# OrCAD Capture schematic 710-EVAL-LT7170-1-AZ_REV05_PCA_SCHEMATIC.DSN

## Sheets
1 PAGE3
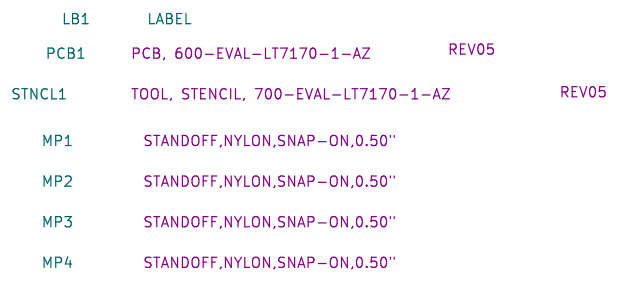
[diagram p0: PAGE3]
2 PAGE1: size Custom; title: WITH DIGITAL POWER SYSTEM MANAGEMENT; note: 20A 16V  DUAL PHASE STEP-DOWN SILENT SWITCHER
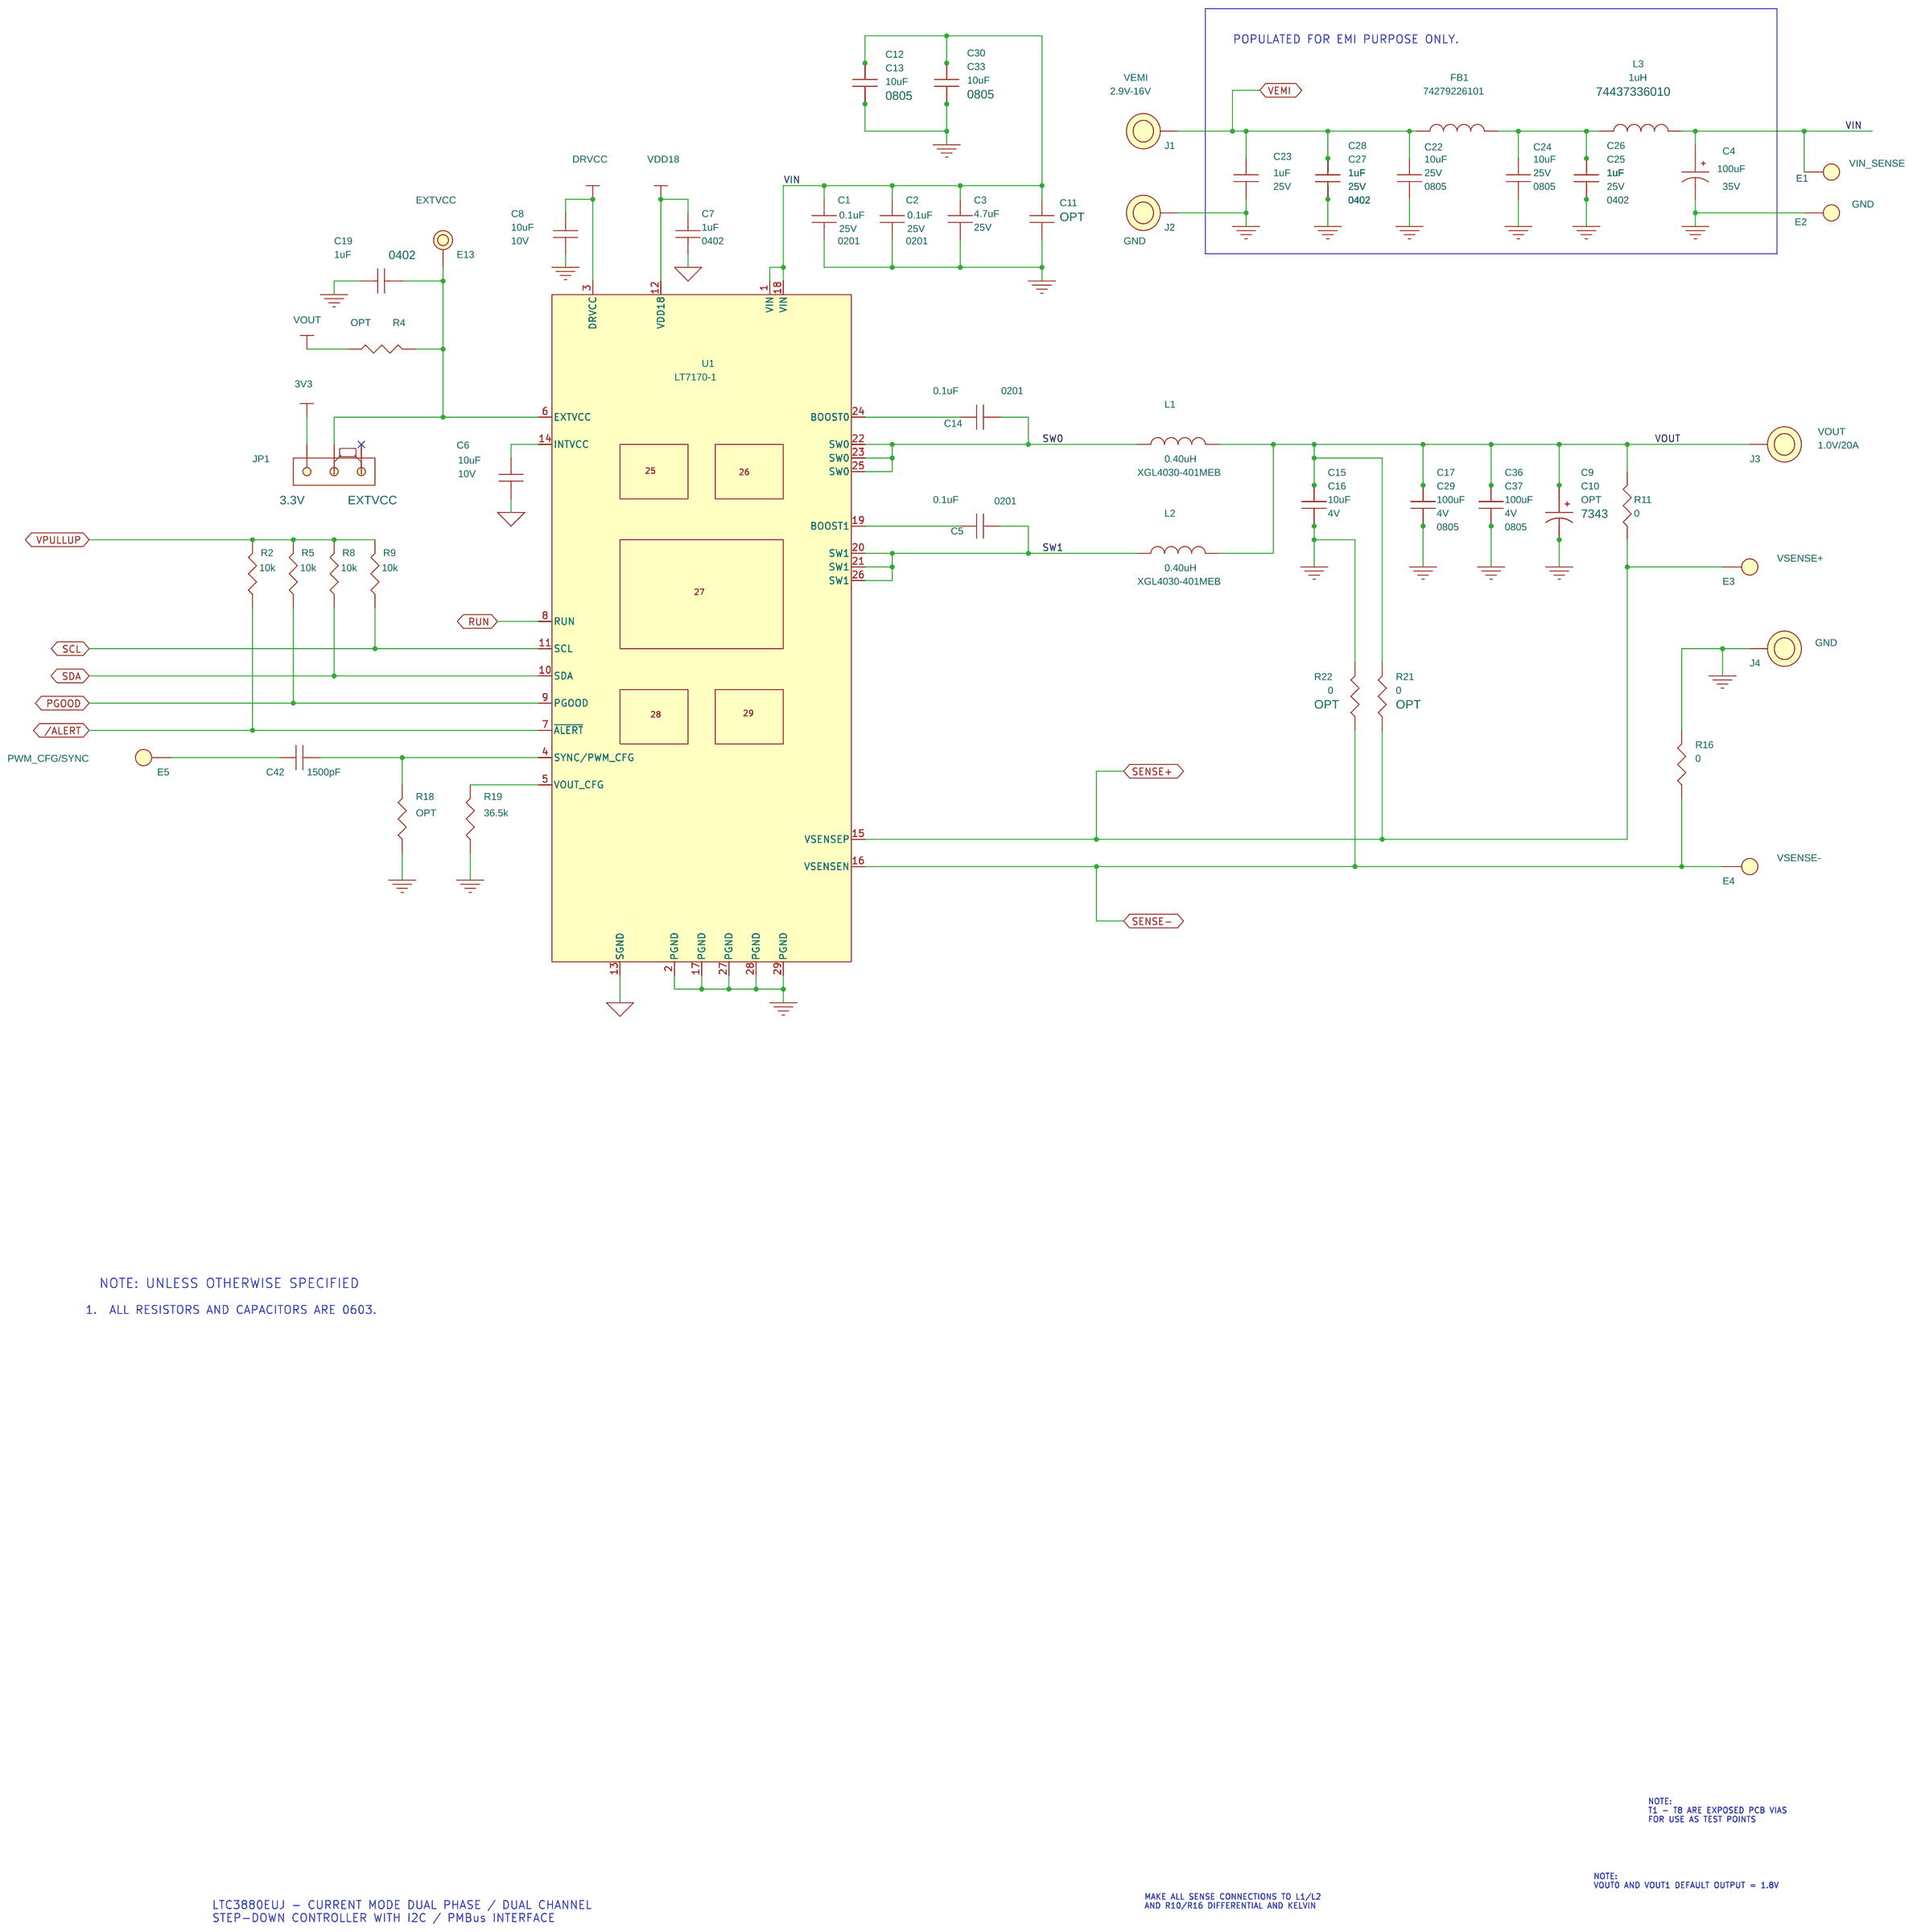
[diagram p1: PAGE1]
3 PAGE2: size Custom; title: WITH DIGITAL POWER SYSTEM MANAGEMENT; note: 20A 16V  DUAL PHASE STEP-DOWN SILENT SWITCHER
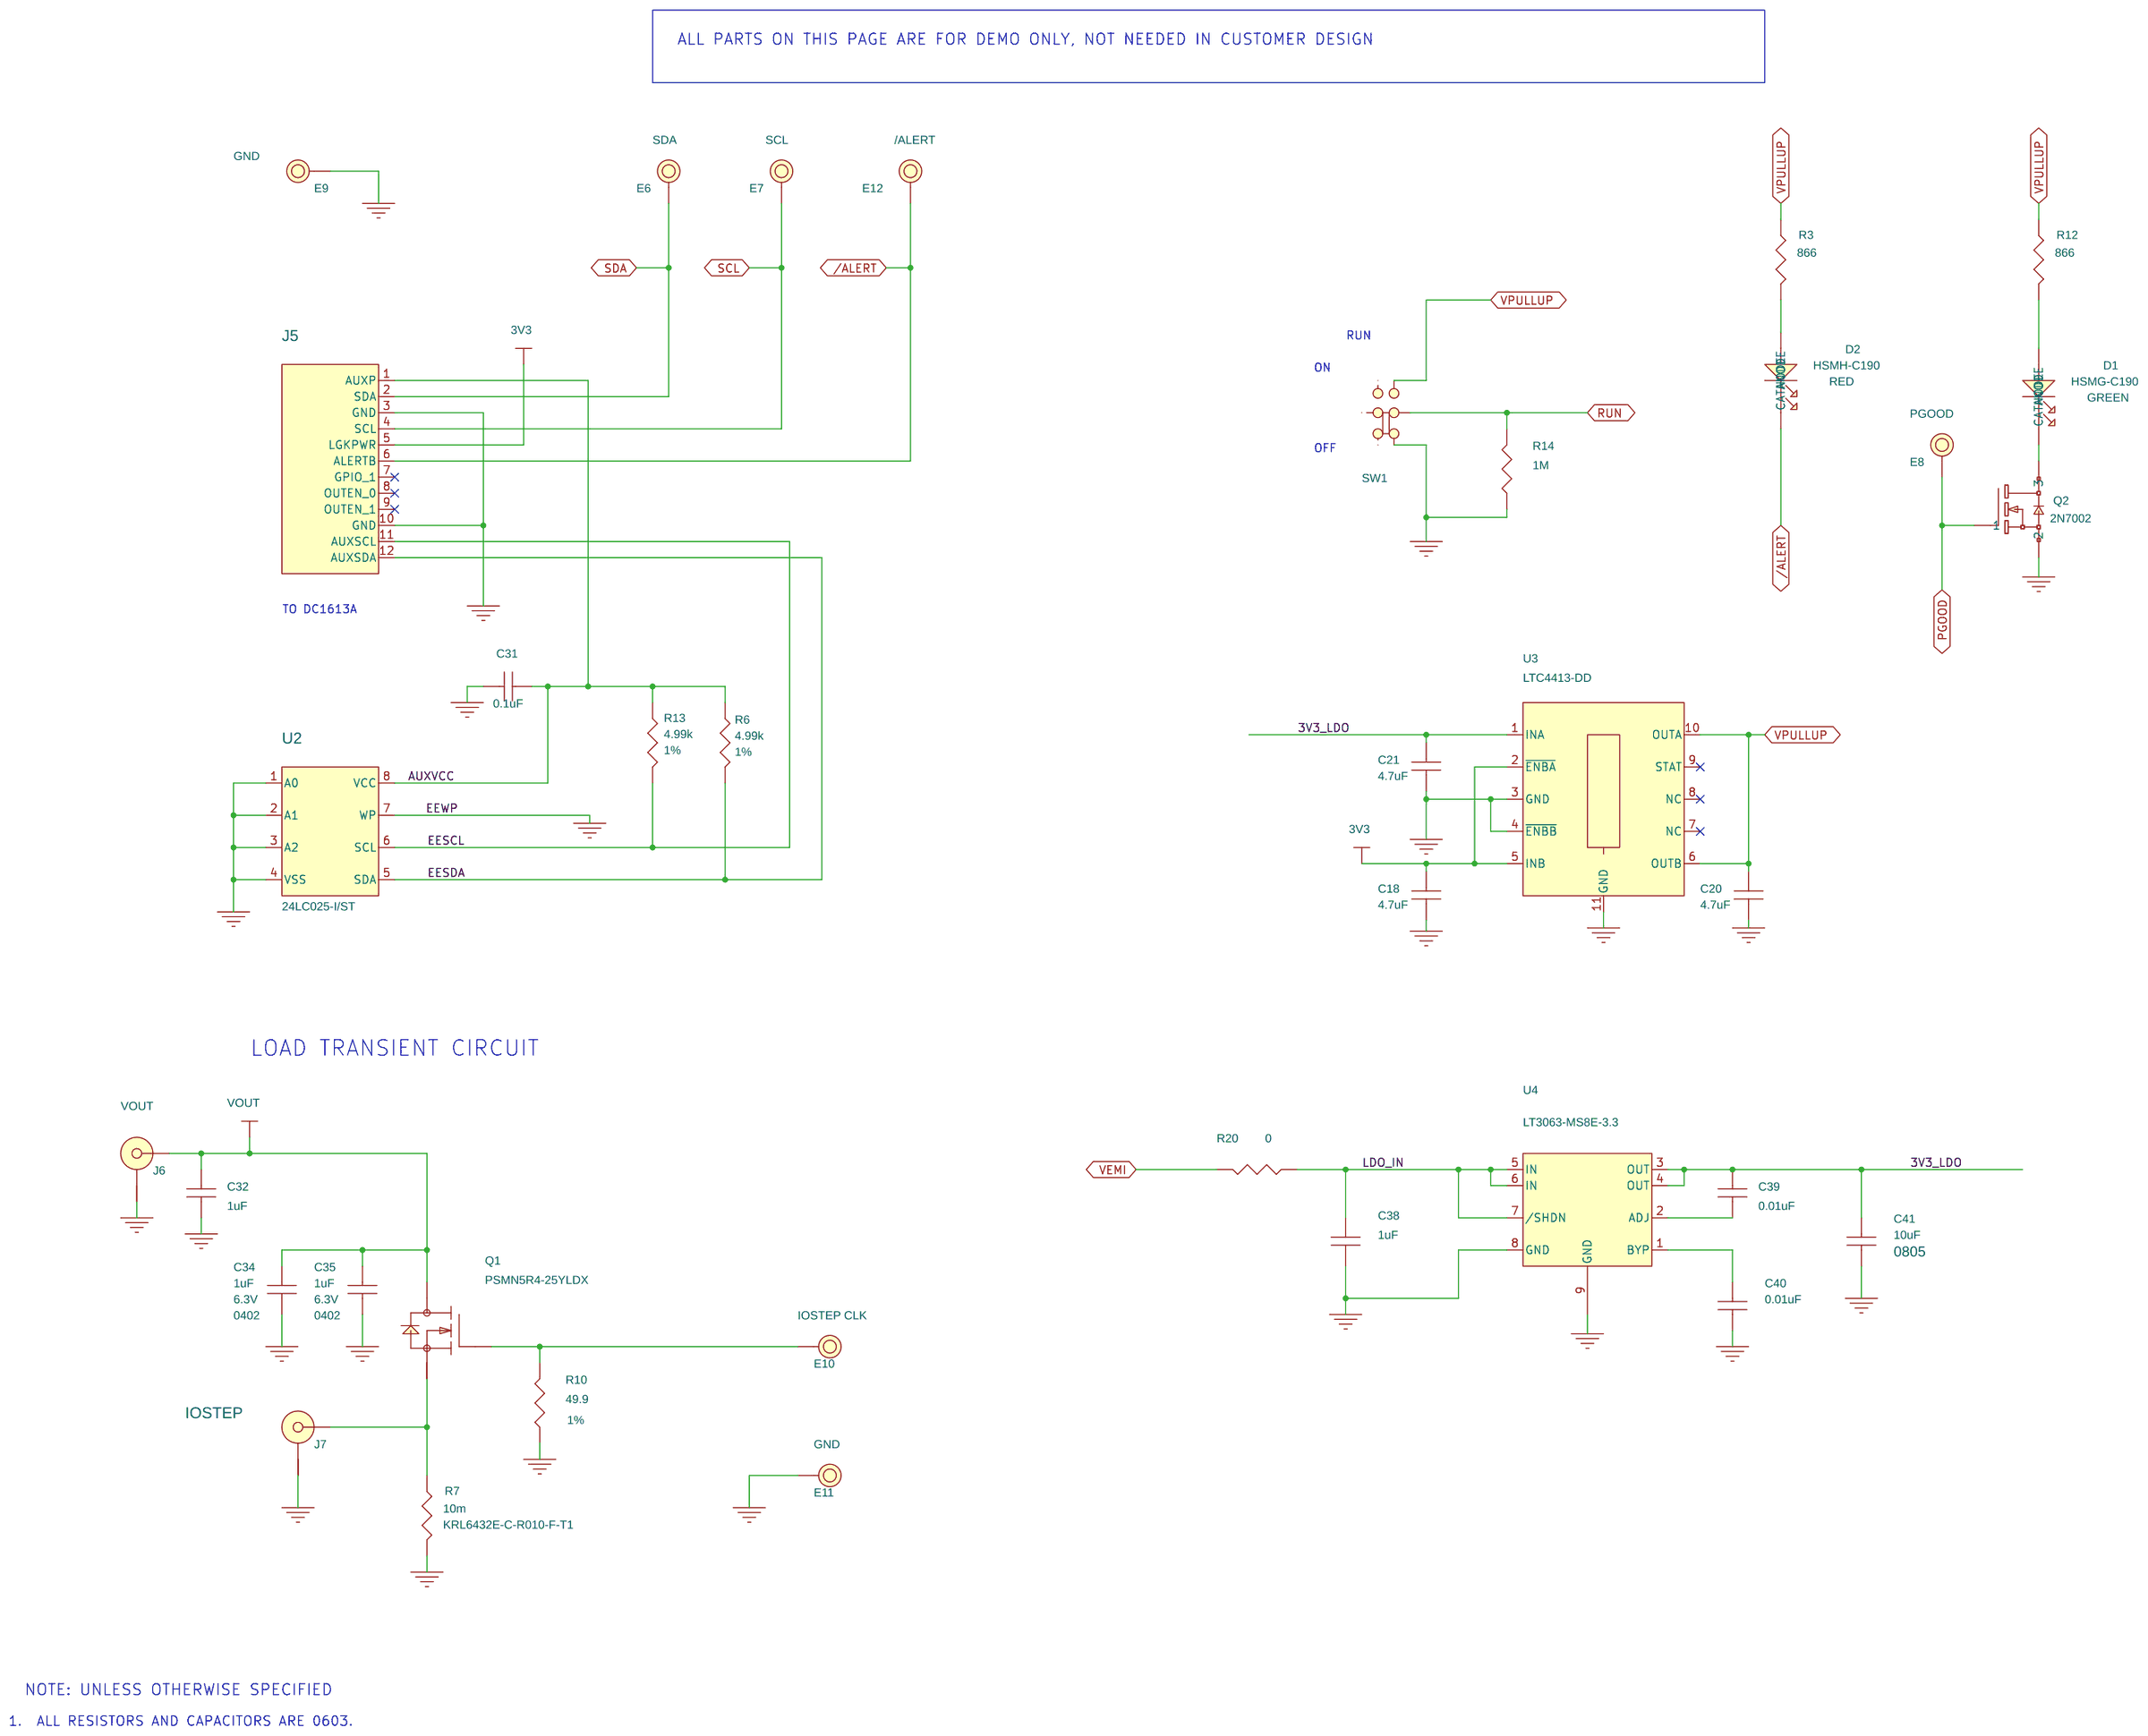
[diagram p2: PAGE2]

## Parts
sheet PAGE1
C1  0.1uF  [CC0201N]
C2  0.1uF  [CC0201N]
C3  4.7uF  [CC0603N]
C4  100uF  [PANASONIC_ZK_6.3X7.7]
C5  0.1uF  [CC0201N]
C6  10uF  [CC0603N]
C7  1uF  [CC0402N]
C8  10uF  [CC0603N]
C9  OPT  [CAPMP7343N]
C10  OPT  [CAPMP7343N]
C11  OPT  [CC0603N]
C12  10uF  [CC0805N]
C13  10uF  [CC0805N]
C14  0.1uF  [CC0201N]
C15  10uF  [CC0603N]
C16  10uF  [CC0603N]
C17  100uF  [CC0805N]
C19  1uF  [CC0402N]
C22  10uF  [CC0805N]
C23  1uF  [CC0603N]
C24  10uF  [CC0805N]
C25  1uF  [CC0402N]
C26  1uF  [CC0402N]
C27  1uF  [CC0402N]
C28  1uF  [CC0402N]
C29  100uF  [CC0805N]
C30  10uF  [CC0805N]
C33  10uF  [CC0805N]
C36  100uF  [CC0805N]
C37  100uF  [CC0805N]
C42  1500pF  [CC0603N]
E1  TEST POINT  [MILLMAX2308]
E2  TEST POINT  [MILLMAX2308]
E3  TEST POINT  [MILLMAX2308]
E4  TEST POINT  [MILLMAX2308]
E5  TEST POINT  [MILLMAX2308]
E13  TEST POINT  [MILLMAX2501]
FB1  100 OHMS@100MHz  [WURTH-74279226101]
J1  BANANA JACK  [KEY-575-4]
J2  BANANA JACK  [KEY-575-4]
J3  BANANA JACK  [KEY-575-4]
J4  BANANA JACK  [KEY-575-4]
JP1  HDR  [HD1X3-079]
L1  0.40uH  [COILCRAFT-XGL4030]
L2  0.40uH  [COILCRAFT-XGL4030]
L3  1uH  [WURTH-74437336010]
R2  10k  [CR0603N]
R4  OPT  [CR0603N]
R5  10k  [CR0603N]
R8  10k  [CR0603N]
R9  10k  [CR0603N]
R11  0  [CR0603N]
R16  0  [CR0603N]
R18  OPT  [CR0603N]
R19  36.5k  [CR0603N]
R21  0  [CR0603N]
R22  0  [CR0603N]
U1  LT7170-1  [LTC-LQFN-24-7065]
XJP1  SHUNT
sheet PAGE2
C18  4.7uF  [CC0603N]
C20  4.7uF  [CC0603N]
C21  4.7uF  [CC0603N]
C31  0.1uF  [CC0603N]
C32  1uF  [CC0402N]
C34  1uF  [CC0402N]
C35  1uF  [CC0402N]
C38  1uF  [CC0603N]
C39  0.01uF  [CC0603N]
C40  0.01uF  [CC0603N]
C41  10uF  [CC0805N]
D1  GREEN  [LED_0603]
D2  RED  [LED_0603]
E6  TEST POINT  [MILLMAX2501]
E7  TEST POINT  [MILLMAX2501]
E8  TEST POINT  [MILLMAX2501]
E9  TEST POINT  [MILLMAX2501]
E10  TEST POINT  [MILLMAX2501]
E11  TEST POINT  [MILLMAX2501]
E12  TEST POINT  [MILLMAX2501]
J5  HDR,SHROUDED  [HD2X6-079-MOLEX]
J6  RF,BNC  [CONNEX-112404]
J7  RF,BNC  [CONNEX-112404]
Q1  PSMN5R4-25YLDX  [NXP-LFPAK56]
Q2  2N7002  [SOT23-3N]
R3  866  [CR0603N]
R6  4.99k  [CR0603N]
R7  10m  [SUSUMU-KRL6432]
R10  49.9  [CR0603N]
R12  866  [CR0603N]
R13  4.99k  [CR0603N]
R14  1M  [CR0603N]
R20  0  [CR0603N]
SW1  DPDT  [CK-JS202011CQN]
U2  24LC025-I/ST  [MICROCHIP-TSSOP-8]
U3  LTC4413-DD  [LTC-DD-10-1699]
U4  LT3063-MS8E-3.3  [LTC-MS8E-8-1662]
sheet PAGE3
LB1  LABEL  [895-0154_REV01]
MP1  STANDOFF  [KEYSTONE_8829-8834]
MP2  STANDOFF  [KEYSTONE_8829-8834]
MP3  STANDOFF  [KEYSTONE_8829-8834]
MP4  STANDOFF  [KEYSTONE_8829-8834]
PCB1  PCB, 600-EVAL-LT7170-1-AZ
STNCL1  TOOL,STENCIL,700-EVAL-LT7170

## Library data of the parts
C1 C2 = CAP: CAP.,0.1uF,X6S,25V,10%,0201; CLASS: DISCRETE; Component: cap; Dielectric Type: X6S; FPLIST: CC0201N,CC0201L,CC0201M; Inventory Qty: 0; Manufacturer: Taiyo Yuden; Manufacturer PN: TMK063C6104KP-F; PART_NUMBER: 150-1861; Package Size: 0201; Part Number: TDK C3216X5R1E476M160AC; Part Type: CAP1206; Rated Voltage: 25V; Tolerance: 10%
C3 = CAP: CAP.,4.7uF,X6S,25V,10%,0603; CLASS: DISCRETE; Component: cap; Dielectric Type: X6S; FPLIST: CC0603N,CC0603L,CC0603M; Inventory Qty: 0; Manufacturer: MURATA; Manufacturer PN: GRM188C81E475KE11D; PART_NUMBER: 150-0798; Package Size: 0603; Part Number: TDK C3216X5R1E476M160AC; Part Type: CAP1206; Rated Voltage: 25V; Tolerance: 10%
C4 = CAP_P: CAP.,100uF,ALUM,35V,20%,SMD,AEC-Q200; CLASS: DISCRETE; Dielectric Type: ALUM; Inventory Qty: 0; Manufacturer: PANASONIC; Manufacturer PN: EEHZK1V101XP; PART_NUMBER: 150-1440; Package Size: SMD; Part Number: PANASONIC EEHZK1V101XP; Rated Voltage: 35V; Tolerance: 20%
C5 C14 = CAP: CAP.,0.1uF,X6S,25V,10%,0201; CLASS: DISCRETE; Component: cap; Dielectric Type: X6S; FPLIST: CC0201N,CC0201L,CC0201M; Inventory Qty: 0; Manufacturer: Taiyo Yuden; Manufacturer PN: TMK063C6104KP-F; PART_NUMBER: 150-1861; Package Size: 0201; Part Number: AVX 04023D104KAT2A; Rated Voltage: 25V; Tolerance: 10%
C6 = CAP: CAP.,10uF,X6S,10V,10%,0603,Interposer Termination,NO SUBS ALLOWED; CLASS: DISCRETE; Component: cap; Dielectric Type: X6S; FPLIST: CC0603N,CC0603L,CC0603M; Inventory Qty: 0; Manufacturer: MURATA; Manufacturer PN: ZRB18AC81A106KE01L; PART_NUMBER: 150-0797; Package Size: 0603; Part Number: TDK C3216X5R1E476M160AC; Part Type: CAP1206; Rated Voltage: 10V; Tolerance: 10%
C7 = CAP: CAP.,1uF,X7S,10V,10%,0402; CLASS: DISCRETE; Dielectric Type: X7S; FPLIST: CC0402N,CC0402L,CC0402M; Inventory Qty: 300; Manufacturer: MURATA; Manufacturer PN: GRM155C71A105KE11D; PART_NUMBER: 150-1445; Package Size: 0402; Part Number: MURATA ZRB18AC81A106KE01L; Rated Voltage: 10V; Tolerance: 10%
C8 = CAP: CAP.,10uF,X6S,10V,10%,0603,Interposer Termination,NO SUBS ALLOWED; CLASS: DISCRETE; Dielectric Type: X6S; FPLIST: CC0603N,CC0603L,CC0603M; Inventory Qty: 0; Manufacturer: MURATA; Manufacturer PN: ZRB18AC81A106KE01L; PART_NUMBER: 150-0797; Package Size: 0603; Part Number: MURATA ZRB18AC81A106KE01L; Rated Voltage: 10V; Tolerance: 10%
C9 C10 = CAP_P: CAP., OPTION, 7343; CLASS: DISCRETE; FPLIST: CAPMP7343N,CAPMP7343L,CAPMP7343M; PART_NUMBER: 150-0067; Package Size: 7343; Package Type: SMD; Part Number: OPTION
C11 = CAP: CAP., OPTION, 0603; CLASS: DISCRETE; Component: cap; FPLIST: CC0603N,CC0603L,CC0603M; PART_NUMBER: 150-3038; Package Size: 0603; Package Type: SMD; Part Number: TDK C3216X5R1E476M160AC; Part Type: CAP1206
C12 = CAP: CAP.,10uF,X7S,25V,10%,0805; CLASS: DISCRETE; Component: cap; Dielectric Type: X7S; FPLIST: CC0805N,CC0805L,CC0805M; Inventory Qty: 3000; Manufacturer: MURATA; Manufacturer PN: GRM21BC71E106KE11L; PART_NUMBER: 150-1813; Package Size: 0805; Package Type: SMD; Part Number: TDK C3216X5R1E476M160AC; Rated Voltage: 25V; Tolerance: 10%
C13 C30 C33 = CAP: CAP.,10uF,X7S,25V,10%,0805; CLASS: DISCRETE; Component: cap; Dielectric Type: X7S; FPLIST: CC0805N,CC0805L,CC0805M; Inventory Qty: 3000; Manufacturer: MURATA; Manufacturer PN: GRM21BC71E106KE11L; PART_NUMBER: 150-1813; Package Size: 0805; Package Type: SMD; Part Number: TDK C3216X5R1E476M160AC; Part Type: CAP1206; Rated Voltage: 25V; Tolerance: 10%
C15 C16 = CAP: CAP.,10uF,X7S,4V,20%,0603; CLASS: DISCRETE; Dielectric Type: X7S; FPLIST: CC0603N,CC0603L,CC0603M; Inventory Qty: 4000; Manufacturer: TDK; Manufacturer PN: C1608X7S0G106M080AB; PART_NUMBER: 150-1816; Package Size: 0603; Part Number: AVX 12106D107KAT2A; Rated Voltage: 4V; Temperature Coefficient: X7S; Tolerance: 20%
C17 C29 C36 C37 = CAP: CAP.,100uF,X6S,4V,20%,0805; CLASS: DISCRETE; Dielectric Type: X6S; FPLIST: CC0805N,CC0805L,CC0805M; Inventory Qty: 0; Manufacturer: MURATA; Manufacturer PN: GRM21BC80G107ME15L; PART_NUMBER: 150-0960; Package Size: 0805; Package Type: Surface Mount, MLCC; Part Number: AVX 12106D107KAT2A; Rated Voltage: 4V; Tolerance: 20%
C19 = CAP: CAP.,1uF,X7S,10V,10%,0402,AEC-Q200,NO SUBS. ALLOWED; CLASS: DISCRETE; Dielectric Type: X7S; FPLIST: CC0402N,CC0402L,CC0402M; Inventory Qty: 10000; Manufacturer: MURATA; Manufacturer PN: GCM155C71A105KE38D; PART_NUMBER: 150-0594; Package Size: 0402; Part Number: MURATA ZRB18AC81A106KE01L; Rated Voltage: 10V; Temperature Coefficient: X7S; Tolerance: 10%
C22 C24 = CAP: CAP.,10uF,X7S,25V,10%,0805; CLASS: DISCRETE; Dielectric Type: X7S; FPLIST: CC0805N,CC0805L,CC0805M; Inventory Qty: 3000; Manufacturer: MURATA; Manufacturer PN: GRM21BC71E106KE11L; PART_NUMBER: 150-1813; Package Size: 0805; Package Type: SMD; Part Number: TDK C3225X5R1H106K250AB; Rated Voltage: 25V; Tolerance: 10%
C23 = CAP: CAP.,1uF,X5R,25V,10%,0603; CLASS: DISCRETE; Dielectric Type: X5R; FPLIST: CC0603N,CC0603L,CC0603M; Inventory Qty: 24080; Manufacturer: AVX; Manufacturer PN: 06033D105KAT2A; PART_NUMBER: 150-0247; Package Size: 0603; Part Number: TDK CGA3E3X5R1H105K080AB; Rated Voltage: 25V; Tolerance: 10%
C25-C28 = CAP: CAP.,1uF,X5R,25V,10%,0402,NO SUBS ALLOWED; CLASS: DISCRETE; Dielectric Type: X5R; FPLIST: CC0402N,CC0402L,CC0402M; Inventory Qty: 10000; Manufacturer: MURATA; Manufacturer PN: GRM155R61E105KA12D; PART_NUMBER: 150-0822; Package Size: 0402; Part Number: MURATA GCM155R71H104KE02D; Rated Voltage: 25V; Tolerance: 10%
C42 = CAP: CAP.,1500pF,X7R,25V,10%,0603; CLASS: DISCRETE; Dielectric Type: X7R; FPLIST: CC0603N,CC0603L,CC0603M; Inventory Qty: 21092; Manufacturer: AVX; Manufacturer PN: 06033C152KAT2A; PART_NUMBER: 150-3370; Package Size: 0603; Rated Voltage: 25V; Tolerance: 10%
E1 = TEST_POINT_.156_MILL-MAX_2308: TEST POINT,TURRET,0.064" MTG. HOLE,PCB 0.062" THK; CLASS: IO; FPLIST: MILLMAX2308,MILLMAX2308-2; Inventory Qty: 1142083; Manufacturer: MILL-MAX; Manufacturer PN: 2308-2-00-80-00-00-07-0; PART_FIELD_1: VIN_SENSE; PART_NUMBER: 260-0004
E2 = TEST_POINT_.156_MILL-MAX_2308: TEST POINT,TURRET,0.064" MTG. HOLE,PCB 0.062" THK; CLASS: IO; FPLIST: MILLMAX2308,MILLMAX2308-2; Inventory Qty: 1142083; Manufacturer: MILL-MAX; Manufacturer PN: 2308-2-00-80-00-00-07-0; PART_FIELD_1: GND; PART_NUMBER: 260-0004
E3 = TEST_POINT_.156_MILL-MAX_2308: TEST POINT,TURRET,0.064" MTG. HOLE,PCB 0.062" THK; CLASS: IO; FPLIST: MILLMAX2308,MILLMAX2308-2; Inventory Qty: 1142083; Manufacturer: MILL-MAX; Manufacturer PN: 2308-2-00-80-00-00-07-0; PART_FIELD_1: VSENSE+; PART_NUMBER: 260-0004
E4 = TEST_POINT_.156_MILL-MAX_2308: TEST POINT,TURRET,0.064" MTG. HOLE,PCB 0.062" THK; CLASS: IO; FPLIST: MILLMAX2308,MILLMAX2308-2; Inventory Qty: 1142083; Manufacturer: MILL-MAX; Manufacturer PN: 2308-2-00-80-00-00-07-0; PART_FIELD_1: VSENSE-; PART_NUMBER: 260-0004
E5 = TEST_POINT_.156_MILL-MAX_2308: TEST POINT,TURRET,0.064" MTG. HOLE,PCB 0.062" THK; CLASS: IO; FPLIST: MILLMAX2308,MILLMAX2308-2; Inventory Qty: 1142083; Manufacturer: MILL-MAX; Manufacturer PN: 2308-2-00-80-00-00-07-0; PART_FIELD_1: PWM_CFG/SYNC; PART_NUMBER: 260-0004
E13 = TESTPOINT_.219_MILL-MAX_2501: TEST POINT,TURRET,0.094" MTG. HOLE,PCB 0.062" THK; CLASS: IO; Inventory Qty: 823526; Manufacturer: MILL-MAX; Manufacturer PN: 2501-2-00-80-00-00-07-0; PART_FIELD_01: EXTVCC; PART_NUMBER: 260-0003; Part Number: MILL-MAX 2501-2-00-80-00-00-07-0
FB1 = IND: IND.,100 OHMS@100MHz,FERRITE BEAD,25%,8A,6mOHMS,1812; CLASS: DISCRETE; Inventory Qty: 3043; Manufacturer: WURTH ELEKTRONIK; Manufacturer PN: 74279226101; PART_NUMBER: 200-0280; Package Size: 1812; Part Number: WURTH ELEKTRONIK 74279226101; Tolerance: 25%
J1 = BANANA_KEYSTONE-575-4: CONN.,BANANA JACK,FEMALE,THT,NON-INSULATED,SWAGE,0.218"; 1ST PART FIELD: 2.9V-16V; 2nd Part Field: VEMI; CLASS: IO; Inventory Qty: 203061; Manufacturer: KEYSTONE; Manufacturer PN: 575-4; PART_NUMBER: 250-0428
J2 = BANANA_KEYSTONE-575-4: CONN.,BANANA JACK,FEMALE,THT,NON-INSULATED,SWAGE,0.218"; 1ST PART FIELD: GND; CLASS: IO; Inventory Qty: 203061; Manufacturer: KEYSTONE; Manufacturer PN: 575-4; PART_NUMBER: 250-0428
J3 = BANANA_KEYSTONE-575-4: CONN.,BANANA JACK,FEMALE,THT,NON-INSULATED,SWAGE,0.218"; CLASS: IO; Inventory Qty: 203061; Manufacturer: KEYSTONE; Manufacturer PN: 575-4; PART_FIELD_01: VOUT; PART_NUMBER: 250-0428; Part_Field_02: 1.0V/20A
J4 = BANANA_KEYSTONE-575-4: CONN.,BANANA JACK,FEMALE,THT,NON-INSULATED,SWAGE,0.218"; CLASS: IO; Inventory Qty: 203061; Manufacturer: KEYSTONE; Manufacturer PN: 575-4; PART_FIELD_01: GND; PART_NUMBER: 250-0428; Part Number: MILL-MAX 2501-2-00-80-00-00-07-0
JP1 = 1X3: CONN.,HDR,MALE,1x3,2mm,VERT,ST,THT,NO SUBS. ALLOWED; 1st Part Field: 3.3V; 2nd Part Field: EXTVCC; CLASS: IO; Inventory Qty: 28997; Manufacturer: Wurth Elektronik; Manufacturer PN: 62000311121; PART_NUMBER: 250-0639
L1 L2 = IND: IND.,0.40uH,PWR,20%,22.5A,32.8mOHMS,SMD,AEC-Q200; CLASS: DISCRETE; Inventory Qty: 0; Manufacturer: COILCRAFT; Manufacturer PN: XGL4030-401MEB; PART_NUMBER: 200-0422; Package Size: SMD; Tolerance: 20%
L3 = IND: IND.,SHIELDED,1uH,20%,7.3A,14mOHMS,5030; CLASS: DISCRETE; Inventory Qty: 0; Manufacturer: WURTH ELEKTRONIK; Manufacturer PN: 74437336010; PART_NUMBER: TMP-8292; Package Size: 5030; Tolerance: 20%
R2 R5 R8 R9 = RES: RES.,10k OHMS,1%,1/10W,0603,AEC-Q200; CLASS: DISCRETE; FPLIST: CR0603N,CR0603L,CR0603M; Inventory Qty: 194448; Manufacturer: VISHAY; Manufacturer PN: CRCW060310K0FKEA; PART_NUMBER: 100-2012; Package Size: 0603; Part Number: VISHAY CRCW060310K0FKEA; Part Type: CR0402; Rated Power: 1/10W; Temperature Coefficient: +/-100ppm/C; Tolerance: 1%
R4 = RES: RES., OPTION, 0603; CLASS: DISCRETE; FPLIST: CR0603N,CR0603L,CR0603M; PART_NUMBER: 100-2374; Package Size: 0603; Part Number: OPTION
R11 R16 = RES: RES.,0 OHM,1/10W,0603,AEC-Q200; CLASS: DISCRETE; FPLIST: CR0603N,CR0603L,CR0603M; Inventory Qty: 676258; Manufacturer: VISHAY; Manufacturer PN: CRCW06030000Z0EA; PART_NUMBER: 100-0009; Package Size: 0603; Part Number: VISHAY CRCW06030000Z0EA; Rated Power: 1/10W
R18 = RES: RES., OPTION, 0603; CLASS: DISCRETE; FPLIST: CR0603N,CR0603L,CR0603M; PART_NUMBER: 100-2374; Package Size: 0603; Part Type: CR0402
R19 = RES: RES.,36.5k OHMS,1%,1/10W,0603; CLASS: DISCRETE; FPLIST: CR0603N,CR0603L,CR0603M; Inventory Qty: 32942; Manufacturer: VISHAY; Manufacturer PN: CRCW060336K5FKEA; PART_NUMBER: 100-0337; Package Size: 0603; Part Number: TBD; Part Type: CR0402; Rated Power: 1/10W; Temperature Coefficient: 100ppm; Tolerance: 1%
R21 R22 = RES: RES.,0 OHM,1/10W,0603,AEC-Q200; BOM Notes: OPT; CLASS: DISCRETE; FPLIST: CR0603N,CR0603L,CR0603M; Inventory Qty: 700742; Manufacturer: VISHAY; Manufacturer PN: CRCW06030000Z0EA; PART_NUMBER: 100-0009; Package Size: 0603; Part Number: VISHAY CRCW06030000Z0EA; Rated Power: 1/10W
U1 = LT7170-1-LQFN_1: IC,REGULATOR,LQFN-24, 12A,16V  DUAL PHASE STEP-DOWN SILENT SWITCHER; CLASS: IC; Inventory Qty: 0; Manufacturer: ANALOG DEVICES; Manufacturer PN: LT7170RV-1#TRPBF; PART_NUMBER: LOCAL-LT7170-1-LQFN; Package Type: LQFN
XJP1 = SHUNT_2MM: CONN.,SHUNT,FEMALE,2-POS,2mm; CLASS: IO; Inventory Qty: 64675; Manufacturer: Wurth Elektronik; Manufacturer PN: 60800213421; PART_NUMBER: 250-0485; Part Number: Wurth Elektronik 60800213421
C18 C20 C21 = CAP: CAP.,4.7uF,X5R,25V,10%,0603; CLASS: DISCRETE; Dielectric Type: X5R; FPLIST: CC0603N,CC0603L,CC0603M; Inventory Qty: 10846; Manufacturer: MURATA; Manufacturer PN: GRM188R61E475KE15D; PART_NUMBER: 150-0445; Package Size: 0603; Part Number: TDK C1608X7S0J475K080AC; Rated Voltage: 25V; Tolerance: 10%
C31 = CAP: CAP.,0.1uF,X7R,10V,20%,0603; CLASS: DISCRETE; Dielectric Type: X7R; FPLIST: CC0603N,CC0603L,CC0603M; Inventory Qty: 17762; Manufacturer: AVX; Manufacturer PN: 0603ZC104MAT2A; PART_NUMBER: 150-3258; Package Size: 0603; Part Number: AVX 0603ZC104MAT2A; Rated Voltage: 10V; Tolerance: 20%
C32 C34 C35 = CAP: CAP.,1uF,X7R,6.3V,10%,0402; CLASS: DISCRETE; Dielectric Type: X7R; FPLIST: CC0402N,CC0402L,CC0402M; Inventory Qty: 20000; Manufacturer: MURATA; Manufacturer PN: GRM155R70J105KA12D; PART_NUMBER: 150-2328; Package Size: 0402; Part Number: MURATA GCM188R71H103KA37D; Rated Voltage: 6.3V; Tolerance: 10%
C38 = CAP: CAP.,1uF,X7R,50V,10%,0603; CLASS: DISCRETE; Dielectric Type: X7R; FPLIST: CC0603N,CC0603L,CC0603M; Inventory Qty: 15823; Manufacturer: AVX; Manufacturer PN: 06035C105KAT2A; PART_NUMBER: 150-2333; Package Size: 0603; Part Number: MURATA GCM188R71H103KA37D; Rated Voltage: 50V; Tolerance: 10%
C39 C40 = CAP: CAP.,0.01uF,X7R,25V,10%,0603,AEC-Q200; CLASS: DISCRETE; Dielectric Type: X7R; FPLIST: CC0603N,CC0603L,CC0603M; Inventory Qty: 54846; Manufacturer: AVX; Manufacturer PN: 06033C103K4Z2A; PART_NUMBER: 150-0440; Package Size: 0603; Part Number: MURATA GCM188R71H103KA37D; Rated Voltage: 25V; Tolerance: 10%
C41 = CAP: CAP.,10uF,X7R,10V,10%,0805; CLASS: DISCRETE; Dielectric Type: X7R; FPLIST: CC0805N,CC0805L,CC0805M; Inventory Qty: 25564; Manufacturer: AVX; Manufacturer PN: 0805ZC106KAT2A; PART_NUMBER: 150-3001; Package Size: 0805; Part Number: MURATA GCM188R71H103KA37D; Rated Voltage: 10V; Tolerance: 10%
D1 = LED: LED,GREEN,DIFFUSED,0603; CLASS: DISCRETE; Inventory Qty: 5000; Manufacturer: BROADCOM INC.; Manufacturer PN: HSMG-C190; PART_NUMBER: 270-0131; Package Type: 0603; Part Number: WURTH ELEK. 150060GS75000
D2 = LED: LED,RED,DIFFUSED,0603; CLASS: DISCRETE; Inventory Qty: 4000; Manufacturer: BROADCOM INC.; Manufacturer PN: HSMH-C190; PART_NUMBER: 270-0156; Package Type: 0603; Part Number: WURTH ELEK. 150060GS75000
E6 = TESTPOINT_.219_MILL-MAX_2501: TEST POINT,TURRET,0.094" MTG. HOLE,PCB 0.062" THK; CLASS: IO; Inventory Qty: 823526; Manufacturer: MILL-MAX; Manufacturer PN: 2501-2-00-80-00-00-07-0; PART_FIELD_01: SDA; PART_NUMBER: 260-0003; Part Number: MILL-MAX 2501-2-00-80-00-00-07-0
E7 = TESTPOINT_.219_MILL-MAX_2501: TEST POINT,TURRET,0.094" MTG. HOLE,PCB 0.062" THK; CLASS: IO; Inventory Qty: 823526; Manufacturer: MILL-MAX; Manufacturer PN: 2501-2-00-80-00-00-07-0; PART_FIELD_01: SCL; PART_NUMBER: 260-0003; Part Number: MILL-MAX 2501-2-00-80-00-00-07-0
E8 = TESTPOINT_.219_MILL-MAX_2501: TEST POINT,TURRET,0.094" MTG. HOLE,PCB 0.062" THK; CLASS: IO; Inventory Qty: 823526; Manufacturer: MILL-MAX; Manufacturer PN: 2501-2-00-80-00-00-07-0; PART_FIELD_01: PGOOD; PART_NUMBER: 260-0003; Part Number: MILL-MAX 2501-2-00-80-00-00-07-0
E9 E11 = TESTPOINT_.219_MILL-MAX_2501: TEST POINT,TURRET,0.094" MTG. HOLE,PCB 0.062" THK; CLASS: IO; Inventory Qty: 823526; Manufacturer: MILL-MAX; Manufacturer PN: 2501-2-00-80-00-00-07-0; PART_FIELD_01: GND; PART_NUMBER: 260-0003; Part Number: MILL-MAX 2501-2-00-80-00-00-07-0
E10 = TESTPOINT_.219_MILL-MAX_2501: TEST POINT,TURRET,0.094" MTG. HOLE,PCB 0.062" THK; CLASS: IO; Inventory Qty: 823526; Manufacturer: MILL-MAX; Manufacturer PN: 2501-2-00-80-00-00-07-0; PART_FIELD_01: IOSTEP CLK; PART_NUMBER: 260-0003; Part Number: MILL-MAX 2501-2-00-80-00-00-07-0
E12 = TESTPOINT_.219_MILL-MAX_2501: TEST POINT,TURRET,0.094" MTG. HOLE,PCB 0.062" THK; CLASS: IO; Inventory Qty: 823526; Manufacturer: MILL-MAX; Manufacturer PN: 2501-2-00-80-00-00-07-0; PART_FIELD_01: /ALERT; PART_NUMBER: 260-0003; Part Number: MILL-MAX 2501-2-00-80-00-00-07-0
J5 = CONN._FCI_12_POS_2MM: CONN.,HDR,SHROUDED,MALE,2x6,2mm,VERT,ST,THT; CLASS: IO; FPLIST: HD2X6-079-MOLEX,AMPHENOL-FCI-9814-X06-12; Inventory Qty: 12768; Manufacturer: AMPHENOL; Manufacturer PN: 98414-G06-12ULF; PART_NUMBER: 250-0433; Part Number: FCI 98414-G06-12ULF
J6 = BNC_50_OHM_112404_B: CONN.,RF,BNC,RCPT,JACK,5-PIN,ST,THT,50 OHMS; 1ST PART FIELD: VOUT; CLASS: IO; Inventory Qty: 80023; Manufacturer: AMPHENOL RF; Manufacturer PN: 112404; PART_NUMBER: 250-0427; Part Number: AMPHENOL RF 112404
J7 = BNC_50_OHM_112404_B: CONN.,RF,BNC,RCPT,JACK,5-PIN,ST,THT,50 OHMS; 1ST PART FIELD: IOSTEP; CLASS: IO; Inventory Qty: 80023; Manufacturer: AMPHENOL RF; Manufacturer PN: 112404; PART_NUMBER: 250-0427; Part Number: AMPHENOL RF 112404
Q1 = 5P_N-CH_TYPE1D_0: XSTR.,MOSFET,N-CH,25V,70A,LFPAK55,Power-SO8; CLASS: DISCRETE; Inventory Qty: 1456; Manufacturer: NEXPERIA; PART_NUMBER: 240-0436; Package Size: SC-100, SOT-669; Package Type: LFPAK55,Power-SO8; Rated Power: 47W (Tc); Rated Voltage: 25V
Q2 = 2N7002_SOT-23: XSTR.,MOSFET,N-CH,60V,300mA,SOT-23-3 (TO-236); CLASS: DISCRETE; Inventory Qty: 6460; Manufacturer: VISHAY; Manufacturer PN: 2N7002K-T1-GE3; PART_NUMBER: 240-0125; Package Size: SOT-23; Package Type: SOT-23-3 (TO-236); Part Number: VISHAY 2N7002K-T1-GE3; Rated Voltage: 60V
R3 R12 = RES: RES.,866 OHMS,1%,1/10W,0603,AEC-Q200; CLASS: DISCRETE; FPLIST: CR0603N,CR0603L,CR0603M; Inventory Qty: 30000; Manufacturer: VISHAY; Manufacturer PN: CRCW0603866RFKEA; PART_NUMBER: 100-0436; Package Size: 0603; Part Number: VISHAY CRCW0603200RFKEA; Rated Power: 1/10W; Temperature Coefficient: 100ppm; Tolerance: 1%
R6 R13 = RES: RES.,4.99k OHMS,1%,1/10W,0603,AEC-Q200; CLASS: DISCRETE; FPLIST: CR0603N,CR0603L,CR0603M; Inventory Qty: 89391; Manufacturer: PANASONIC; Manufacturer PN: ERJ3EKF4991V; PART_NUMBER: 100-2510; Package Size: 0603; Part Number: VISHAY CRCW06034K99FKEA; Rated Power: 1/10W; Temperature Coefficient: 100ppm; Tolerance: 1%
R7 = RES: RES.,10m OHMS,1%,3W,6.3 X3.1mm,AEC-Q200 LONG-SIDE TERM; CLASS: DISCRETE; Inventory Qty: 0; Manufacturer: SUSUMU; Manufacturer PN: KRL6432E-C-R010-F-T1; PART_NUMBER: 100-1792; Package Size: 6.3 X3.1mm; Rated Power: 3W; Temperature Coefficient: 50PPM; Tolerance: 1%
R10 = RES: RES.,49.9 OHMS,1%,1/10W,0603; CLASS: DISCRETE; FPLIST: CR0603N,CR0603L,CR0603M; Inventory Qty: 58078; Manufacturer: PANASONIC; Manufacturer PN: ERJ3EKF49R9V; PART_NUMBER: 100-0115; Package Size: 0603; Part Number: VISHAY CRCW060310K0FKEA; Rated Power: 1/10W; Temperature Coefficient: +/-100ppm; Tolerance: 1%
R14 = RES: RES.,1M OHM,1%,1/10W,0603,AEC-Q200; CLASS: DISCRETE; FPLIST: CR0603N,CR0603L,CR0603M; Inventory Qty: 31399; Manufacturer: NIC; Manufacturer PN: NRC06F1004TRF; PART_NUMBER: 100-0119; Package Size: 0603; Part Number: VISHAY CRCW060310R0JNEA; Rated Power: 1/10W; Temperature Coefficient: 100ppm/C; Tolerance: 1%
R20 = RES: RES.,0 OHM,1/10W,0603,AEC-Q200; CLASS: DISCRETE; FPLIST: CR0603N,CR0603L,CR0603M; Inventory Qty: 676258; Manufacturer: VISHAY; Manufacturer PN: CRCW06030000Z0EA; PART_NUMBER: 100-0009; Package Size: 0603; Part Number: VISHAY CRCW060310R0JNEA; Rated Power: 1/10W
SW1 = SW-DPDT-JS202011CQN_ALT4: SWITCH,SLIDE,DPDT,0.3A,6VDC,PTH; CLASS: DISCRETE; Inventory Qty: 32171; Manufacturer: C&K; Manufacturer PN: JS202011CQN; PART_NUMBER: 430-0039
U2 = 24LC025-I_ST_TSSOP-8: IC, MEMORY,EEPROM,2Kb (256x8),TSSOP-8,400kHz; CLASS: IC; Inventory Qty: 19510; Manufacturer: Microchip; PART_NUMBER: 380-0087; Package Size: TSSOP-8; Package Type: TSSOP-8; Part Number: MICROCHIP 24LC025-I/ST
U3 = LTC4413-DD: IC,DUAL 2.6A, 2.5V-5.5V IDEAL DIO,10DFN; CLASS: IC; Inventory Qty: 0; Manufacturer: ANALOG DEVICES; Manufacturer PN: LTC4413EDD#PBF; PART_NUMBER: LTC4413EDD#PBF; Package Size: 3mmX3mm; Package Type: 10DFN
U4 = LT3063-MS8E-X: IC,200mA LDO LINEAR REGULATOR,MSOP-8 (MS8E); CLASS: IC; Inventory Qty: 0; Manufacturer: LINEAR TECH.; Manufacturer PN: LT3063EMS8E-3.3#PBF; PART_NUMBER: LT3063EMS8E-3.3#PBF; Package Type: MSOP-8 (MS8E)
LB1 = BLANK_LABEL: LABEL SPEC, DEMO BOARD SERIAL NUMBER; Inventory Qty: 0; Manufacturer: BRADY; Manufacturer PN: THT-96-717-10; PART_NUMBER: 895-0154
MP1-MP4 = BLANK_MECHANICAL_PART: STANDOFF,NYLON,SNAP-ON,0.50"; CLASS: DISCRETE; Inventory Qty: 214842; Manufacturer: KEYSTONE; Manufacturer PN: 8833; PART_NUMBER: 763-0007
PCB1 = BLANK_PCB_PART: BOM Notes: REV05; CLASS: DISCRETE; Inventory Qty: 0; Manufacturer: ADI APPROVED SUPPLIER; Manufacturer PN: 600-EVAL-LT7170-1-AZ; PART_NUMBER: 600-EVAL-LT7170-1-AZ
STNCL1 = BLANK_STENCIL_PART: TOOL, STENCIL, 700-EVAL-LT7170-1-AZ; BOM Notes: REV05; CLASS: DISCRETE; Inventory Qty: 0; Manufacturer: ADI APPROVED SUPPLIER; Manufacturer PN: 830-EVAL-LT7170-1-AZ; PART_NUMBER: 830-EVAL-LT7170-1-AZ

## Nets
3V3: C18.1 J5.5(LGKPWR) JP1.1 U3.2(~{ENBA}) U3.5(INB)
3V3_LDO: C21.1 C39.1 C41.1 U3.1(INA) U4.3(OUT) U4.4(OUT)
GND: C1.2 C2.2 C3.2 C4.2 C8.1 C9.2 C10.2 C11.2 C12.2 C13.2 C15.2 C16.2 C17.2 C18.2 C19.1 C20.2 C21.2 C22.2 C23.2 C24.2 C25.2 C26.2 C27.2 C28.2 C29.2 C30.2 C31.2 C32.2 C33.2 C34.2 C35.2 C36.2 C37.2 C38.2 C40.2 C41.2 E2.1(A) E9.1 E11.1 J2.1 J4.1 J5.3(GND) J5.10(GND) J6.2 J6.3 J6.4 J6.5 J7.2 J7.3 J7.4 J7.5 Q2.2 R7.2 R10.1 R14.1 R16.1 R18.2 R19.2 R22.1 SW1.3 U1.2(PGND) U1.17(PGND) U1.27(PGND) U1.28(PGND) U1.29(PGND) U2.1(A0) U2.2(A1) U2.3(A2) U2.4(VSS) U2.7(WP) U3.3(GND) U3.4(~{ENBB}) U3.11(GND) U4.8(GND) U4.9(GND)
GND_SIGNAL: C6.2 C7.1 U1.13(SGND)
VDD18: C7.2 U1.12(VDD18)
VIN: C1.1 C2.1 C3.1 C4.1 C11.1 C12.1 C13.1 C30.1 C33.1 E1.1(A) L3.2 U1.1(VIN) U1.18(VIN)
/ALERT: D2.1(CATHODE) E12.1 J5.6(ALERTB) R2.1 U1.7(~{ALERT})
AUXVCC: C31.1 J5.1(AUXP) R6.1 R13.1 U2.8(VCC)
DRVCC: C8.2 U1.3(DRVCC)
EESCL: J5.11(AUXSCL) R13.2 U2.6(SCL)
EESDA: J5.12(AUXSDA) R6.2 U2.5(SDA)
LDO_IN: C38.1 R20.1 U4.5(IN) U4.6(IN) U4.7(/SHDN)
PGOOD: E8.1 Q2.1 R5.1 U1.9(PGOOD)
RUN: R14.2 SW1.2 U1.8(RUN)
SCL: E7.1 J5.4(SCL) R9.1 U1.11(SCL)
SDA: E6.1 J5.2(SDA) R8.1 U1.10(SDA)
SENSE+: E3.1(A) R11.2 R21.2 U1.15(VSENSEP)
SENSE-: E4.1(A) R16.2 R22.2 U1.16(VSENSEN)
SW0: C14.2 L1.1 U1.22(SW0) U1.23(SW0) U1.25(SW0)
SW1: C5.2 L2.1 U1.20(SW1) U1.21(SW1) U1.26(SW1)
VEMI: C22.1 C23.1 C27.1 C28.1 FB1.1 J1.1 R20.2
VOUT: C9.1 C10.1 C15.1 C16.1 C17.1 C29.1 C32.1 C34.1 C35.1 C36.1 C37.1 J3.1 J6.1 L1.2 L2.2 Q1.5(D) R4.2 R11.1 R21.1
VPULLUP: C20.1 R2.2 R3.1 R5.2 R8.2 R9.2 R12.1 SW1.1 U3.6(OUTB) U3.10(OUTA)
N20910533: R19.1 U1.5(VOUT_CFG)
N20923371: J7.1 Q1.1(S_2) Q1.2(S_1) Q1.3(S) R7.1
N20923421: E10.1 Q1.4(G) R10.2
N20952274: D1.1(CATHODE) Q2.3
N21024045: C24.1 C25.1 C26.1 FB1.2 L3.1
N21117265: C6.1 U1.14(INTVCC)
N21119493: C19.2 E13.1 JP1.2 R4.1 U1.6(EXTVCC)
N21125115: C14.1 U1.24(BOOST0)
N21141698: D2.2(ANODE) R3.2
N21141762: D1.2(ANODE) R12.2
N21236805: C5.1 U1.19(BOOST1)
N21245481: C42.2 R18.1 U1.4(SYNC/PWM_CFG)
N21278483: C39.2 U4.2(ADJ)
N21278486: C40.1 U4.1(BYP)
N21286257: C42.1 E5.1(A)

Not connected (* = marked no-connect by the designer): J5 7(GPIO_1)* 8(OUTEN_0)* 9(OUTEN_1)*; JP1 3*; SW1 4 5 6; U3 7(NC)* 8(NC)* 9(STAT)*

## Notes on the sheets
sheet 2
- POPULATED FOR EMI PURPOSE ONLY.
- NOTE: UNLESS OTHERWISE SPECIFIED
- 1.  ALL RESISTORS AND CAPACITORS ARE 0603.
- NOTE:
  T1 - T8 ARE EXPOSED PCB VIAS
  FOR USE AS TEST POINTS
- NOTE:
  VOUT0 AND VOUT1 DEFAULT OUTPUT = 1.8V
- MAKE ALL SENSE CONNECTIONS TO L1/L2
  AND R10/R16 DIFFERENTIAL AND KELVIN
- LTC3880EUJ - CURRENT MODE DUAL PHASE / DUAL CHANNEL
  STEP-DOWN CONTROLLER WITH I2C / PMBus INTERFACE
sheet 3
- ALL PARTS ON THIS PAGE ARE FOR DEMO ONLY, NOT NEEDED IN CUSTOMER DESIGN
- RUN
- ON
- OFF
- TO DC1613A
- LOAD TRANSIENT CIRCUIT
- NOTE: UNLESS OTHERWISE SPECIFIED
- 1.  ALL RESISTORS AND CAPACITORS ARE 0603.
